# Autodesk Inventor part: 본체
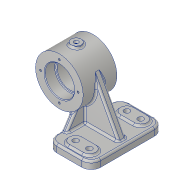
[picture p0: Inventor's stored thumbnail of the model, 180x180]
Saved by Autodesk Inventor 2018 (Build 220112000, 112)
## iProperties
Created: 2023-08
Part Number: 본체
Material: 알루미늄 6061
Document SubType Name: Modeling
Designer: home
Density: 2.7 g/cm^3
Appearance: 알루미늄 - 평지
Mass: 777.596 g
Surface Area: 536.873 cm^2
Volume: 287.998 cm^3
Author: home
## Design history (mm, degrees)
sketch "스케치3"
  geometry: L1 (-27, 0)-(27, 0); L2 (-27, 0)-(-27, 38); L3 (-27, 38)-(27, 38); L4 (27, 38)-(27, 0); L5 (-27, 23.5)-(-10, 23.5); L6 (-10, 23.5)-(-10, 20.5); L7 (-10, 20.5)-(10, 20.5); L8 (10, 20.5)-(10, 23.5); L9 (10, 23.5)-(27, 23.5); 2 further points
  constraints: 18 end point, 5 perpendicular, 4 point on line, 2 horizontal, 1 coincident, 1 midpoint, 1 vertical
  dimensions: "d1" = 54 distance of L1.start L1.end; "d2" = 76 diameter of L3 L1; "d3" = 17 distance of L5.end L5.start; "d4" = 17 distance of L8.end L9.end; "d5" = 41 diameter of L7 L1; "d6" = 47 diameter of L5 L1
revolve "회전1" sketch "스케치3" stored, may be unused: angle "d7" = 90 deg
node "작업 평면1"
sketch "스케치4"
  geometry: L1 (27, -38)-(-27, -38) reference; L2 (-58, 12)-(58, 12); L3 (58, 12)-(58, 82); L4 (58, 82)-(-58, 82); L5 (-58, 82)-(-58, 12); 1 further point
  constraints: 8 end point, 2 parallel, 1 horizontal, 1 perpendicular
  dimensions: "d9" = 116 distance of L4.end L3.end; "d10" = 70 distance of L3.end L2.end; "d11" = 120 distance between parallel lines of L4 L1; "d12" = 58 distance from line of point (0, 0) L5
extrude "돌출1" join sketch "스케치4" distance "d13" = 12; taper "d14" = 0 deg
node "작업 평면2"
sketch "스케치5"
  geometry: C1 r 8 at (0, 0); 1 further point
  constraints: 1 centre point, 1 coincident
  dimensions: "d16" = 16 diameter of C1
extrude "돌출2" join sketch "스케치5" stored distance "d17" = 12; taper "d18" = 0 deg
sketch "스케치6"
  geometry: C1 r 8 at (0, 0) reference; 1 further point
  constraints: 1 coincident
hole "구멍1" sketch "스케치6" at (0, 0) diameter "d19" = 5.188; stored, may be unused: countersink angle "d23" = 90 deg, drill point angle "d25" = 118 deg; dims "d20" = 12, "d21" = 7, "d22" = 4, "d24" = 16
sketch "스케치8"
  geometry: C1 r 23.5 at (0, 0) reference; C2 r 38 at (0, 0) reference; A1 r 30 centre (0, 0) between (0, 30) and (30, 0); 2 further points
  constraints: 4 point on circle, 2 horizontal alignment, 2 vertical alignment, 1 centre point, 1 coincident
  dimensions: "d30" = 60 diameter of A1
hole "구멍2" sketch "스케치8" at (0, 30), (30, 0), (0, -30), (-30, 0) diameter "d31" = 3.242; stored, may be unused: countersink angle "d35" = 90 deg, drill point angle "d37" = 118 deg; dims "d32" = 8, "d33" = 7, "d34" = 4, "d36" = 10
sketch "스케치9"
  geometry: L1 (41, -8)-(37.148, -8) reference; L2 (37.148, 8)-(41, 8) reference; L3 (41, 8)-(41, 3.5) reference; L4 (41, 3.5)-(37, 3.5) reference; L5 (37, 3.5)-(37, 2.594) reference; L6 (37, 2.594)-(20.335, 2.594) reference; L7 (20.335, -2.594)-(37, -2.594) reference; L8 (37, -2.594)-(37, -3.5) reference; L9 (37, -3.5)-(41, -3.5) reference; L10 (41, -3.5)-(41, -8) reference; L11 (-58, 12)-(-70, 12) reference; L12 (-70, 12)-(-70, 82) reference; L13 (-70, 82)-(-58, 82) reference; L14 (-58, 82)-(-58, 12) reference; L15 (17.882, 33.529)-(-58, 74); L16 (-58, 12)-(-36.056, 12); A1 r 38 centre (0, 0) between (37.148, 8) and (37.148, -8) reference; A2 r 20.5 centre (0, 0) between (20.335, 2.594) and (20.335, -2.594) reference; A3 r 38 centre (0, 0) between (17.882, 33.529) and (-36.056, 12); 1 further point
  constraints: 6 end point, 4 point on circle, 1 centre point, 1 coincident, 1 horizontal, 1 point on line, 1 tangent
  dimensions: "d38" = 8 distance of L13.end L15.end
extrude "돌출3" join sketch "스케치9" stored distance "d39" = 12; taper "d40" = 0 deg
sketch "스케치15"
  geometry: L1 (58, -12)-(-58, -12) reference; L2 (7.5, -12)-(-7.5, -12); L3 (-7.5, -12)-(-7.5, -20); L4 (-7.5, -20)-(7.5, -20); L5 (7.5, -20)-(7.5, -12); 1 further point
  constraints: 8 end point, 2 parallel, 1 horizontal, 1 perpendicular, 1 point on line
  dimensions: "d57" = 8 distance of L2.end L3.end; "d58" = 15 distance of L3.end L4.end; "d87" = 7.5 distance from line of point (0, 0) L5
extrude "돌출6" join sketch "스케치15" stored distance "d60" = 8; taper "d61" = 0 deg
sketch "스케치16"
  geometry: L1 (0, 0)-(0, 12) reference; L2 (48, 53.379)-(68, 53.379) reference; L3 (68, 53.379)-(68, 49.795) reference; L4 (68, 49.795)-(85, 49.795) reference; L5 (85, 49.795)-(85, 33.944) reference; L6 (85, 33.944)-(65.5, 33.944) reference; L7 (116, 12)-(116, 0) reference; L8 (116, 0)-(0, 0) reference; L9 (0, 0)-(0, 12) reference; L10 (0, 12)-(50.5, 12) reference; L11 (48, 49.795)-(48, 53.379) reference; L12 (31, 49.795)-(48, 49.795) reference; L13 (31, 33.944)-(31, 49.795) reference; L14 (50.5, 33.944)-(31, 33.944) reference; L15 (31, 106.056)-(85, 106.056) reference; L16 (85, 106.056)-(85, 90.205) reference; L17 (85, 90.205)-(68, 90.205) reference; L18 (68, 90.205)-(68, 86.621) reference; L19 (68, 86.621)-(48, 86.621) reference; L20 (48, 86.621)-(48, 90.205) reference; L21 (48, 90.205)-(31, 90.205) reference; L22 (31, 90.205)-(31, 106.056) reference; L23 (116, 12)-(0, 12) reference; L24 (36.251, 33.944)-(22, 12); L25 (65.5, 33.944)-(65.5, 12) reference; L26 (65.5, 12)-(116, 12) reference; L27 (50.5, 12)-(50.5, 33.944) reference; L28 (65.5, 33.944)-(50.5, 33.944) reference; 1 further point
  constraints: 2 end point, 2 point on line
  dimensions: "d63" = 22 distance of L24.end L1.end; "d64" = 33 deg angle of L24 L1
feature "리브2" sketch "스케치16" dims "d65" = 1, "d66" = 8, "d67" = 0, "d68" = 0, "d69" = 1, "d70" = 1
fillet "모깎기1" dims "d71" = 15
sketch "스케치17"
  geometry: L1 (-43, -82)-(43, -82) reference; L2 (-31, -40)-(-31, -62); L3 (-51, -40)-(-51, -62); A1 r 10 centre (-41, -62) between (-31, -62) and (-51, -62); A2 r 10 centre (-41, -40) between (-31, -40) and (-51, -40); 1 further point
  constraints: 4 end point, 4 point on circle, 2 centre point, 2 tangent, 2 vertical
  dimensions: "d72" = 20 diameter of A1; "d73" = 20 distance from line of L1 A1.centre; "d74" = 20 diameter of A2; "d75" = 22 distance of A1.centre A2.centre; "d76" = 41 horizontal distance of A1.centre point (0, 0); "d77" = 41 horizontal distance of point (0, 0) A2.centre
extrude "돌출7" join sketch "스케치17" distance "d78" = 3; taper "d79" = 0 deg
sketch "스케치18"
  geometry: C1 r 4.5 at (-41, -40); C2 r 4.5 at (-41, -62); A1 r 10 centre (-41, -62) between (-51, -62) and (-31, -62) reference; A2 r 10 centre (-41, -40) between (-31, -40) and (-51, -40) reference; 1 further point
  constraints: 2 centre point, 2 coincident
  dimensions: "d80" = 9 diameter of C1; "d81" = 9 diameter of C2
extrude "돌출8" cut sketch "스케치18" extent not by distance; stored distance "d82" = 3; taper "d83" = 0 deg
fillet "모깎기2" dims "d84" = 3
fillet "모깎기20" dims "d109" = 3
fillet "모깎기21" dims "d110" = 3
fillet "모깎기22" dims "d111" = 3
sketch "스케치19"
  geometry: L1 (0, 0)-(86, 0) reference; 2 further points
  constraints: 1 vertical alignment, 1 other
  dimensions: "d92" = 19 distance from line of point (43, 19) L1
feature "엠보싱1" sketch "스케치19" dims "d93" = 0.5, "d94" = 0
fillet "모깎기9" dims "d95" = 1
chamfer "모따기1" distance "d96" = 1; stored, may be unused: second distance "d97" = 2, angle "d98" = 45 deg
fillet "모깎기23" dims "d112" = 3
node "솔리드1"
mirror "미러1"
mirror "미러2"
mirror "미러3"
node "절단 모서리 투영2"
node "절단 모서리 투영3"
other parameters: "d15" = -111
